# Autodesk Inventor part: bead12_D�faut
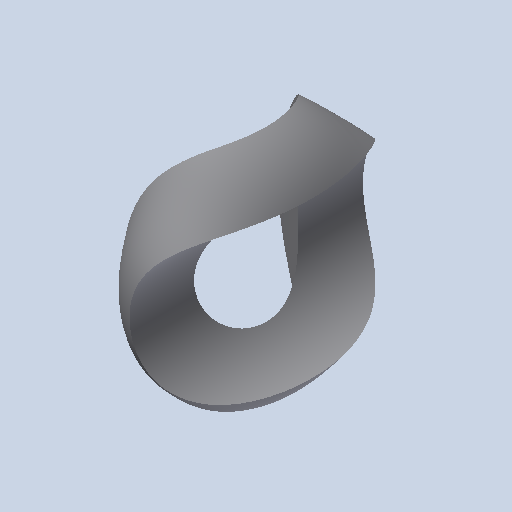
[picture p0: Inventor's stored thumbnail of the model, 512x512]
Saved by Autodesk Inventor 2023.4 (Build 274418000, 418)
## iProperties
Created: 2011-01
Part Number: bead12_D�faut
Document SubType Name: Modeling
Designer: eric
Density: 1 g/cm^3
Mass: 0.132515 g
Surface Area: 2.94553 cm^2
Volume: 0.132515 cm^3
Material: Générique
Appearance: Par défaut
Author: eric
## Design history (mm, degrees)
feature "Base1"
node "Corps solides"
node "Corps surfaciques"
node "Solide1"
